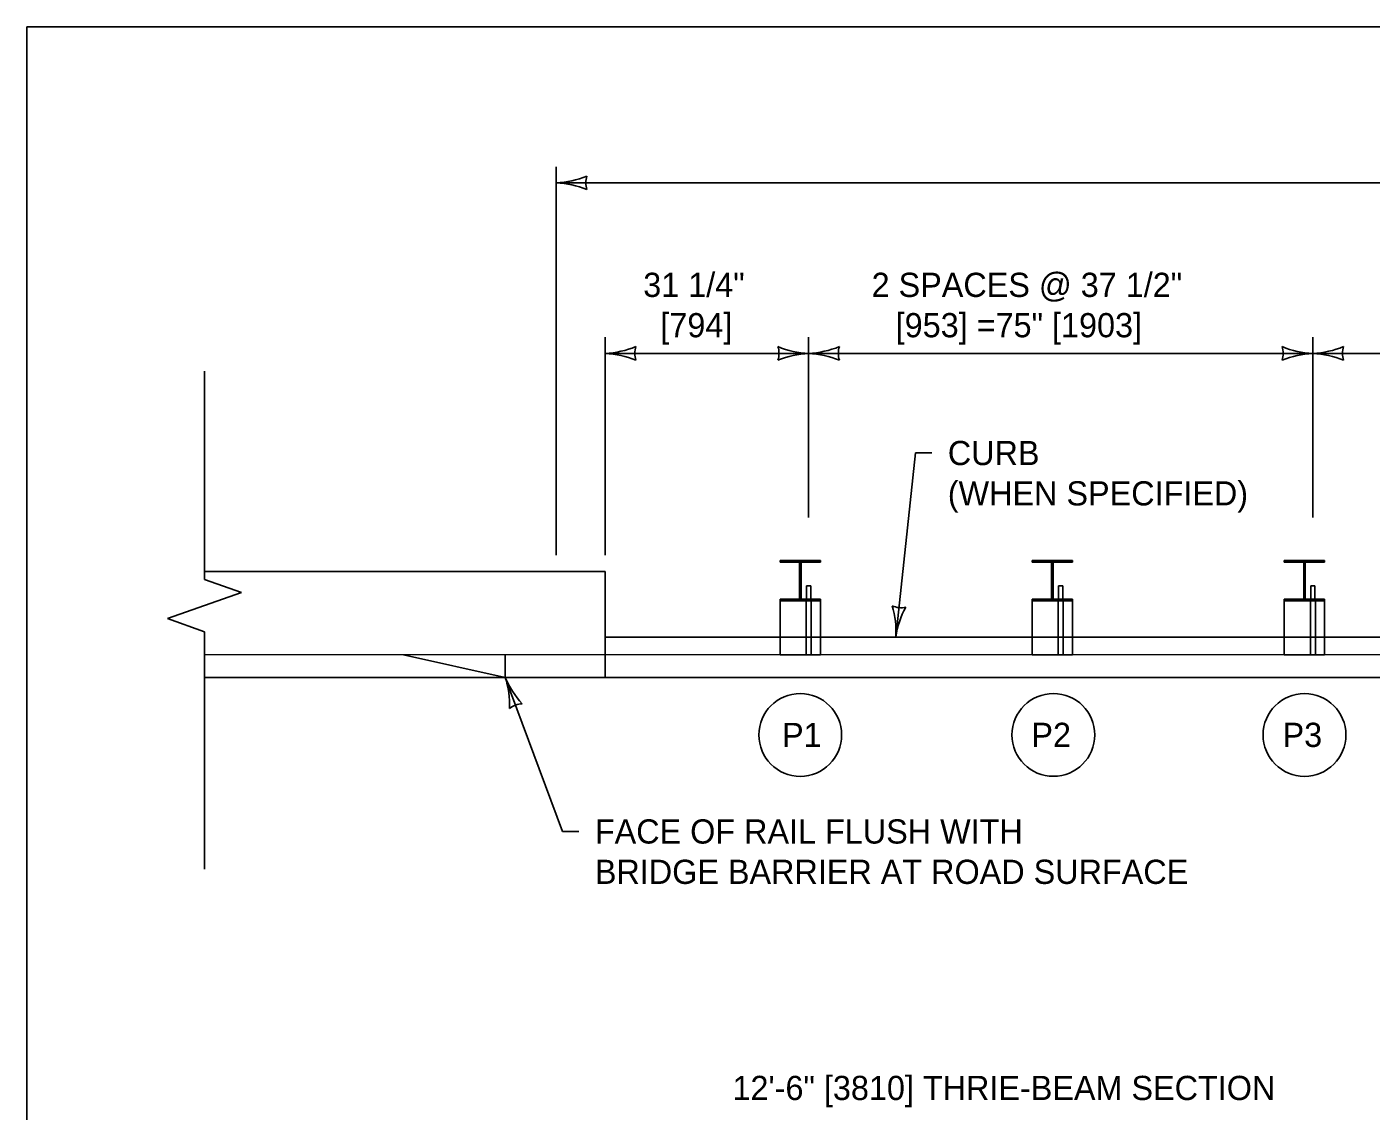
# Model space of a CAD drawing. Extents: x 49991 to 50160, y 49948 to 50051.
# Drawn here: x 49999.384 to 50002.716, y 49996.312 to 49998.999 of the extents above; entities that cross this region are included whole.
import ezdxf

# ---------------------------------------------------------------- set-up
doc = ezdxf.new("R2010")
doc.units = 0
for name, color, linetype in [('Level 1', 7, 'Continuous'), ('Level 2', 7, 'Continuous'), ('Level 3', 7, 'Continuous'), ('Level 4', 7, 'Continuous'), ('Level 6', 7, 'Continuous')]:
    doc.layers.add(name, color=color, linetype=linetype)

msp = doc.modelspace()

# ---------------------------------------------------------------- linework, layer by layer
at = {"layer": 'Level 1'}
for p, q in [((50001.3508, 49997.6765), (50001.2508, 49997.6765)), ((50001.2508, 49997.6765), (50001.2508, 49997.6722)), ((50001.3508, 49997.6722), (50001.2508, 49997.6722)), ((50001.2989, 49997.6722), (50001.2989, 49997.5809)), ((50001.3027, 49997.5809), (50001.3027, 49997.6722)), ((50001.3508, 49997.6722), (50001.3508, 49997.6765)), ((50001.9758, 49997.6765), (50001.8758, 49997.6765)), ((50001.8758, 49997.6765), (50001.8758, 49997.6722)), ((50001.9758, 49997.6722), (50001.8758, 49997.6722)), ((50001.9239, 49997.6722), (50001.9239, 49997.5808)), ((50001.9277, 49997.5808), (50001.9277, 49997.6722)), ((50001.9758, 49997.6722), (50001.9758, 49997.6765)), ((50002.6008, 49997.6765), (50002.5008, 49997.6765)), ((50002.5008, 49997.6765), (50002.5008, 49997.6722)), ((50002.6008, 49997.6722), (50002.5008, 49997.6722)), ((50002.5489, 49997.6722), (50002.5489, 49997.5808)), ((50002.5527, 49997.5808), (50002.5527, 49997.6722)), ((50002.6008, 49997.6722), (50002.6008, 49997.6765)), ((49999.8238, 49997.6496), (50000.8175, 49997.6496)), ((50000.8175, 49997.6496), (50000.8175, 49997.4432)), ((50001.3164, 49997.6142), (50001.3269, 49997.6142)), ((50001.3164, 49997.5809), (50001.3164, 49997.6142)), ((50001.3269, 49997.5809), (50001.3269, 49997.6142)), ((50001.9414, 49997.6142), (50001.9519, 49997.6142)), ((50001.9414, 49997.5808), (50001.9414, 49997.6142)), ((50001.9519, 49997.5808), (50001.9519, 49997.6142)), ((50002.5664, 49997.6142), (50002.5769, 49997.6142)), ((50002.5664, 49997.5808), (50002.5664, 49997.6142)), ((50002.5769, 49997.5808), (50002.5769, 49997.6142)), ((50001.2508, 49997.5809), (50001.2508, 49997.5765)), ((50001.2508, 49997.5809), (50001.3508, 49997.5809)), ((50001.2508, 49997.5765), (50001.3508, 49997.5765)), ((50001.2508, 49997.4432), (50001.2508, 49997.5765)), ((50001.3508, 49997.5765), (50001.2508, 49997.5765)), ((50001.3508, 49997.5765), (50001.3508, 49997.5809)), ((50001.3508, 49997.4432), (50001.3508, 49997.5765)), ((50001.8758, 49997.5808), (50001.8758, 49997.5765)), ((50001.8758, 49997.5808), (50001.9758, 49997.5808)), ((50001.8758, 49997.5765), (50001.9758, 49997.5765)), ((50001.8758, 49997.4432), (50001.8758, 49997.5765)), ((50001.9758, 49997.5765), (50001.8758, 49997.5765)), ((50001.9758, 49997.5765), (50001.9758, 49997.5808)), ((50001.9758, 49997.4432), (50001.9758, 49997.5765)), ((50002.5008, 49997.5808), (50002.5008, 49997.5765)), ((50002.5008, 49997.5808), (50002.6008, 49997.5808)), ((50002.5008, 49997.5765), (50002.6008, 49997.5765)), ((50002.5008, 49997.4432), (50002.5008, 49997.5765)), ((50002.6008, 49997.5765), (50002.5008, 49997.5765)), ((50002.6008, 49997.5765), (50002.6008, 49997.5808)), ((50002.6008, 49997.4432), (50002.6008, 49997.5765)), ((50001.2508, 49997.487), (50000.8175, 49997.487)), ((50001.3508, 49997.487), (50001.8758, 49997.487)), ((50001.9758, 49997.487), (50002.5008, 49997.487)), ((50002.6008, 49997.487), (50002.8133, 49997.487)), ((49999.8238, 49997.4433), (50011.6716, 49997.4428)), ((50000.5693, 49997.387), (50000.3175, 49997.4432)), ((50000.5693, 49997.4432), (50000.5693, 49997.387)), ((50001.3508, 49997.4432), (50001.2508, 49997.4432)), ((50001.9758, 49997.4432), (50001.8758, 49997.4432)), ((50002.6008, 49997.4432), (50002.5008, 49997.4432)), ((49999.8238, 49997.387), (50011.6716, 49997.3866))]:
    msp.add_line(p, q, dxfattribs=at)
msp.add_lwpolyline([(49999.3835, 49998.9992), (50016.7501, 49998.9992), (50016.7501, 49987.7988), (49999.3835, 49987.7988)], close=True, dxfattribs=at)
at = {"layer": 'Level 2'}
for centre in [(50001.3008, 49997.2443), (50001.9283, 49997.2444), (50002.5509, 49997.2443)]:
    msp.add_circle(centre, 0.1026, dxfattribs=at)
at = {"layer": 'Level 3'}
for p, q in [((50000.6956, 49997.6896), (50000.6957, 49998.6527)), ((50000.6957, 49998.6127), (50008.1966, 49998.6127)), ((50000.8175, 49997.6896), (50000.8175, 49998.2299)), ((50001.3216, 49997.7832), (50001.3216, 49998.2299)), ((50002.5716, 49997.7831), (50002.5716, 49998.2299)), ((50001.3216, 49998.1899), (50000.8175, 49998.1899)), ((50001.3216, 49998.1899), (50002.5716, 49998.1899)), ((50002.5716, 49998.1899), (50003.8216, 49998.1899)), ((50001.5376, 49997.487), (50001.5866, 49997.9431)), ((50001.5866, 49997.9431), (50001.6266, 49997.9431)), ((50000.5693, 49997.387), (50000.7116, 49997.0051)), ((50001.3216, 49997.3868), (50000.6966, 49997.3868)), ((50001.3216, 49997.3868), (50000.9925, 49997.3868)), ((50001.9466, 49997.3868), (50001.3216, 49997.3868)), ((50002.5716, 49997.3868), (50001.9466, 49997.3868)), ((50002.8841, 49997.3868), (50002.5716, 49997.3868)), ((50000.7116, 49997.0051), (50000.7516, 49997.0051))]:
    msp.add_line(p, q, dxfattribs=at)
for centre, radius, start, end in [((50000.6842, 49998.8454), 0.233, 272.8273, 292.0772), ((50000.8239, 49998.6127), 0.0548, 162.1388, 197.8612), ((50000.6865, 49998.3905), 0.2223, 67.456, 87.6395), ((50000.806, 49998.4226), 0.233, 272.8273, 292.0772), ((50000.9457, 49998.1899), 0.0548, 162.1388, 197.8612), ((50001.3308, 49998.412), 0.2223, 247.456, 267.6395), ((50001.1934, 49998.1899), 0.0548, 342.1388, 17.8612), ((50001.3102, 49998.4226), 0.233, 272.8273, 292.0772), ((50001.4499, 49998.1899), 0.0548, 162.1388, 197.8612), ((50002.5808, 49998.412), 0.2223, 247.456, 267.6395), ((50002.4434, 49998.1899), 0.0548, 342.1388, 17.8612), ((50002.5602, 49998.4226), 0.233, 272.8273, 292.0772), ((50002.6999, 49998.1899), 0.0548, 162.1388, 197.8612), ((50000.8083, 49997.9678), 0.2223, 67.456, 87.6395), ((50001.3331, 49997.9572), 0.233, 92.8273, 112.0772), ((50001.3125, 49997.9678), 0.2223, 67.456, 87.6395), ((50002.5831, 49997.9572), 0.233, 92.8273, 112.0772), ((50002.5625, 49997.9678), 0.2223, 67.456, 87.6395), ((50001.5513, 49997.6144), 0.0548, 246.0178, 281.7402), ((50001.305, 49997.5003), 0.233, 356.7063, 15.9562), ((50001.7575, 49997.4542), 0.2223, 151.335, 171.5185), ((50000.358, 49997.3181), 0.2223, 357.8814, 18.065), ((50000.7834, 49997.479), 0.233, 203.2527, 222.5026), ((50000.6141, 49997.2669), 0.0548, 92.5643, 128.2866)]:
    msp.add_arc(centre, radius, start, end, dxfattribs=at)
at = {"layer": 'Level 4'}
for p, q in [((50001.3154, 49997.4432), (50001.3154, 49997.5765)), ((50001.3279, 49997.4432), (50001.3279, 49997.5765)), ((50001.9404, 49997.4432), (50001.9404, 49997.5765)), ((50001.9529, 49997.4432), (50001.9529, 49997.5765)), ((50002.5654, 49997.4432), (50002.5654, 49997.5765)), ((50002.5654, 49997.4432), (50002.5654, 49997.5765)), ((50002.5779, 49997.4432), (50002.5779, 49997.5765)), ((50002.5779, 49997.4432), (50002.5779, 49997.5765)), ((50001.2508, 49997.487), (50001.3508, 49997.487)), ((50001.8758, 49997.487), (50001.9758, 49997.487)), ((50002.5008, 49997.487), (50002.6008, 49997.487)), ((50000.8175, 49997.4432), (50000.8175, 49997.3868))]:
    msp.add_line(p, q, dxfattribs=at)
at = {"layer": 'Level 6'}
for p, q in [((49999.8238, 49997.6298), (49999.8238, 49998.1459)), ((49999.8238, 49997.6298), (49999.9152, 49997.5974)), ((49999.8238, 49997.565), (49999.9152, 49997.5974)), ((49999.7324, 49997.5326), (49999.8238, 49997.565)), ((49999.7324, 49997.5326), (49999.8238, 49997.5002)), ((49999.8238, 49997.5002), (49999.8238, 49996.9118))]:
    msp.add_line(p, q, dxfattribs=at)

# ---------------------------------------------------------------- texts
at = {"layer": 'Level 2'}
for s, p in [(' 31 1/4"', (50000.8892, 49998.3299)), ('2 SPACES @ 37 1/2" ', (50001.4777, 49998.3299)), ('[794]', (50000.954, 49998.2299)), ('[953] =75" [1903]', (50001.5374, 49998.2299)), ('CURB', (50001.6666, 49997.9131)), ('(WHEN SPECIFIED)', (50001.6666, 49997.8131)), ('P1', (50001.2557, 49997.2143)), ('P2', (50001.8738, 49997.2145)), ('P3', (50002.4965, 49997.2145)), ('FACE OF RAIL FLUSH WITH', (50000.7916, 49996.9751)), ('BRIDGE BARRIER AT ROAD SURFACE', (50000.7916, 49996.8751)), ('12\'-6" [3810] THRIE-BEAM SECTION', (50001.1328, 49996.3394))]:
    msp.add_text(s, height=0.06, dxfattribs=at).set_placement(p)

doc.saveas('drawing.dxf')
